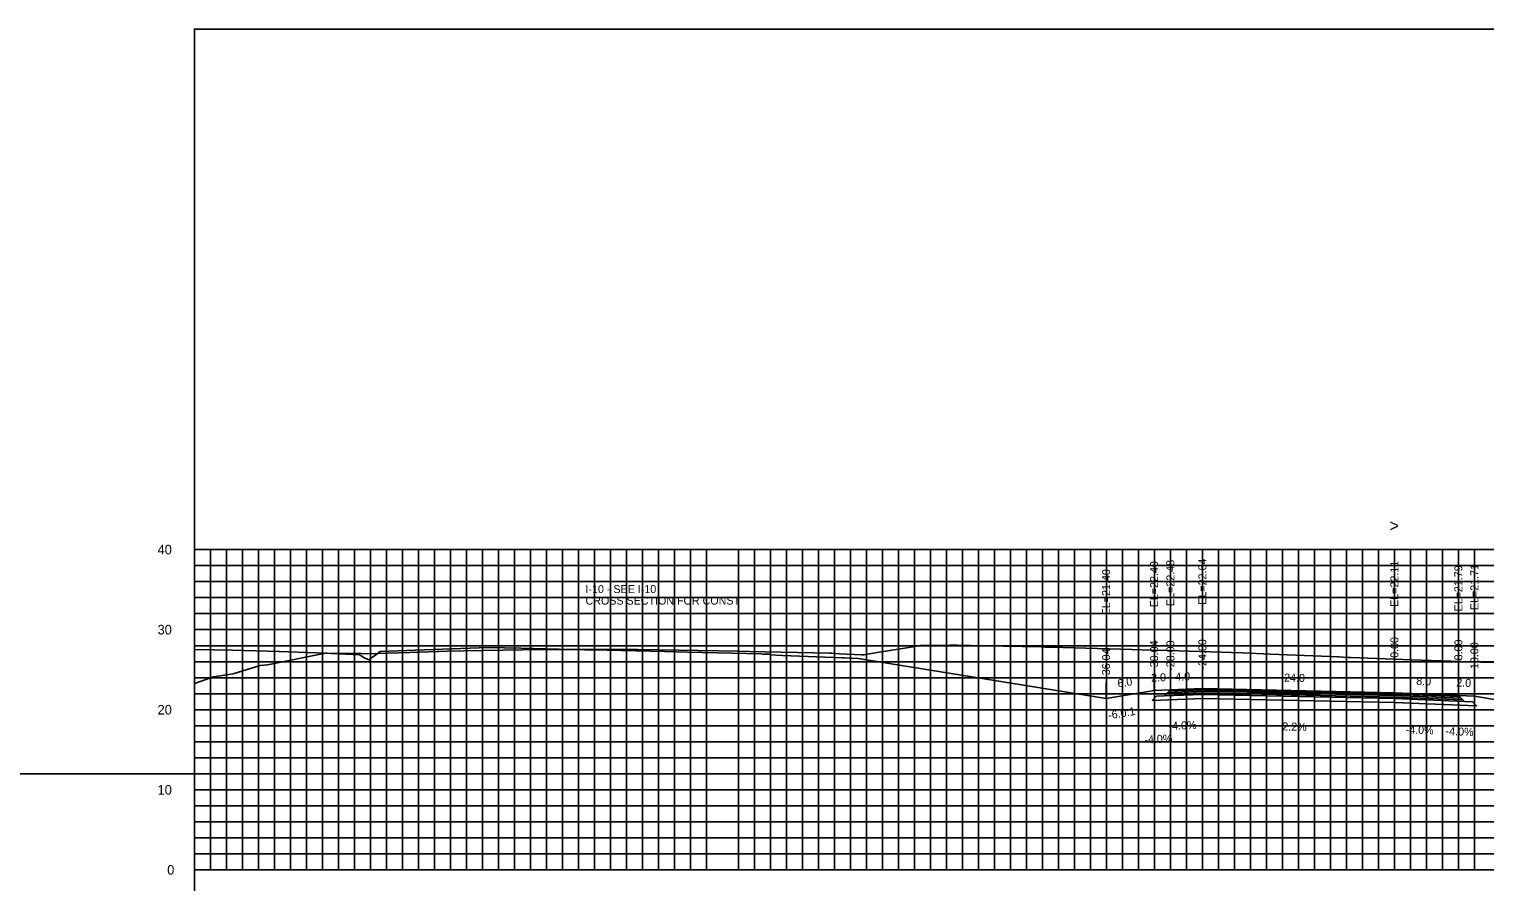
# Model space of a CAD drawing. Extents: x 1800976 to 1805104, y 250057 to 250580.
# Drawn here: x 1802800.3 to 1802982.3, y 250162.9 to 250269.4 of the extents above; entities that cross this region are included whole.
import ezdxf

# ---------------------------------------------------------------- set-up
doc = ezdxf.new("R2010")
doc.units = 0
for name, color, linetype in [('3', 7, 'Continuous'), ('31', 7, 'Continuous'), ('4', 7, 'Continuous'), ('60', 7, 'Continuous'), ('BASE', 7, 'Continuous'), ('CL-CNST', 7, 'Continuous'), ('Level 62', 7, 'Continuous'), ('LOWER BINDER', 7, 'Continuous'), ('M-ROADS', 7, 'Continuous'), ('UPPER BINDER', 7, 'Continuous'), ('WEARING', 7, 'Continuous')]:
    doc.layers.add(name, color=color, linetype=linetype)

msp = doc.modelspace()

# ---------------------------------------------------------------- linework, layer by layer
for p, q in [((1802940.96, 250186.83), (1802940.96, 250188.83)), ((1802943, 250186.91), (1802943, 250188.91)), ((1802947, 250187.07), (1802947, 250189.07)), ((1802971, 250186.54), (1802971, 250188.54)), ((1802934.96, 250185.83), (1802934.96, 250187.83)), ((1802979, 250186.22), (1802979, 250188.22)), ((1802981, 250186.14), (1802981, 250188.14))]:
    msp.add_line(p, q)
msp.add_lwpolyline([(1802821, 250079.43), (1803121, 250079.43), (1803121, 250269.43), (1802821, 250269.43)], close=True)
at = {"layer": '60'}
for p, q in [((1802820.94, 250204.43), (1802821, 250204.43)), ((1802821, 250164.43), (1802821, 250204.43)), ((1802820.94, 250194.43), (1802821, 250194.43)), ((1802820.94, 250184.43), (1802821, 250184.43)), ((1802820.94, 250174.43), (1802821, 250174.43)), ((1802820.94, 250164.43), (1802821, 250164.43)), ((1802821, 250164.43), (1803121, 250164.43)), ((1802821, 250164.37), (1802821, 250164.43)), ((1802831, 250164.37), (1802831, 250164.43)), ((1802841, 250164.37), (1802841, 250164.43)), ((1802851, 250164.37), (1802851, 250164.43)), ((1802861, 250164.37), (1802861, 250164.43)), ((1802871, 250164.37), (1802871, 250164.43)), ((1802881, 250164.37), (1802881, 250164.43)), ((1802891, 250164.37), (1802891, 250164.43)), ((1802901, 250164.37), (1802901, 250164.43)), ((1802911, 250164.37), (1802911, 250164.43)), ((1802921, 250164.37), (1802921, 250164.43)), ((1802931, 250164.37), (1802931, 250164.43)), ((1802941, 250164.37), (1802941, 250164.43)), ((1802951, 250164.37), (1802951, 250164.43)), ((1802961, 250164.37), (1802961, 250164.43)), ((1802971, 250164.37), (1802971, 250164.43)), ((1802981, 250164.37), (1802981, 250164.43))]:
    msp.add_line(p, q, dxfattribs=at)
at = {"layer": 'BASE'}
msp.add_lwpolyline([(1802941.25, 250186.12), (1802942.25, 250186.16), (1802947, 250186.35), (1802971, 250185.82), (1802979.75, 250185.47), (1802980.75, 250185.43), (1802981.27, 250184.91), (1802971, 250185.32), (1802947, 250185.85), (1802940.73, 250185.6)], close=True, dxfattribs=at)
at = {"layer": 'CL-CNST'}
for points in [[(1802821, 250191.96), (1802825.78, 250191.85), (1802831.59, 250191.72), (1802836.32, 250191.52), (1802841.69, 250191.3), (1802842.24, 250190.9), (1802842.95, 250190.61), (1802842.95, 250190.29), (1802842.95, 250190.77), (1802843.5, 250191.17), (1802844.21, 250191.69), (1802849.75, 250191.9), (1802857.71, 250192.2), (1802861.82, 250192.11), (1802869.79, 250191.92), (1802872.58, 250191.86), (1802879.77, 250191.69), (1802882.62, 250191.62), (1802891.88, 250191.4), (1802892.07, 250191.39), (1802892.88, 250191.36), (1802892.9, 250191.35), (1802892.96, 250191.29), (1802894.53, 250191.22), (1802901.96, 250190.92), (1802902.23, 250190.9), (1802903.98, 250190.83), (1802934.96, 250185.83)], [(1802934.96, 250185.83), (1802940.96, 250186.83), (1802943, 250186.91), (1802947, 250187.07), (1802971, 250186.54), (1802979, 250186.22), (1802981, 250186.14), (1803011, 250181.14), (1803015, 250181.14), (1803032.52, 250185.52)]]:
    msp.add_lwpolyline(points, dxfattribs=at)
at = {"layer": 'Level 62'}
for p, q in [((1802821, 250204.43), (1803121, 250204.43)), ((1802821, 250164.43), (1802821, 250204.43)), ((1802823, 250164.43), (1802823, 250204.43)), ((1802825, 250164.43), (1802825, 250204.43)), ((1802827, 250164.43), (1802827, 250204.43)), ((1802829, 250164.43), (1802829, 250204.43)), ((1802831, 250164.43), (1802831, 250204.43)), ((1802833, 250164.43), (1802833, 250204.43)), ((1802835, 250164.43), (1802835, 250204.43)), ((1802837, 250164.43), (1802837, 250204.43)), ((1802839, 250164.43), (1802839, 250204.43)), ((1802841, 250164.43), (1802841, 250204.43)), ((1802843, 250164.43), (1802843, 250204.43)), ((1802845, 250164.43), (1802845, 250204.43)), ((1802847, 250164.43), (1802847, 250204.43)), ((1802849, 250164.43), (1802849, 250204.43)), ((1802851, 250164.43), (1802851, 250204.43)), ((1802853, 250164.43), (1802853, 250204.43)), ((1802855, 250164.43), (1802855, 250204.43)), ((1802857, 250164.43), (1802857, 250204.43)), ((1802859, 250164.43), (1802859, 250204.43)), ((1802861, 250164.43), (1802861, 250204.43)), ((1802863, 250164.43), (1802863, 250204.43)), ((1802865, 250164.43), (1802865, 250204.43)), ((1802867, 250164.43), (1802867, 250204.43)), ((1802869, 250164.43), (1802869, 250204.43)), ((1802871, 250164.43), (1802871, 250204.43)), ((1802873, 250164.43), (1802873, 250204.43)), ((1802875, 250164.43), (1802875, 250204.43)), ((1802877, 250164.43), (1802877, 250204.43)), ((1802879, 250164.43), (1802879, 250204.43)), ((1802881, 250164.43), (1802881, 250204.43)), ((1802883, 250164.43), (1802883, 250204.43)), ((1802885, 250164.43), (1802885, 250204.43)), ((1802889, 250164.43), (1802889, 250204.43)), ((1802891, 250164.43), (1802891, 250204.43)), ((1802893, 250164.43), (1802893, 250204.43)), ((1802895, 250164.43), (1802895, 250204.43)), ((1802897, 250164.43), (1802897, 250204.43)), ((1802899, 250164.43), (1802899, 250204.43)), ((1802901, 250164.43), (1802901, 250204.43)), ((1802903, 250164.43), (1802903, 250204.43)), ((1802905, 250164.43), (1802905, 250204.43)), ((1802907, 250164.43), (1802907, 250204.43)), ((1802909, 250164.43), (1802909, 250204.43)), ((1802911, 250164.43), (1802911, 250204.43)), ((1802913, 250164.43), (1802913, 250204.43)), ((1802915, 250164.43), (1802915, 250204.43)), ((1802917, 250164.43), (1802917, 250204.43)), ((1802919, 250164.43), (1802919, 250204.43)), ((1802921, 250164.43), (1802921, 250204.43)), ((1802923, 250164.43), (1802923, 250204.43)), ((1802925, 250164.43), (1802925, 250204.43)), ((1802927, 250164.43), (1802927, 250204.43)), ((1802929, 250164.43), (1802929, 250204.43)), ((1802931, 250164.43), (1802931, 250204.43)), ((1802933, 250164.43), (1802933, 250204.43)), ((1802935, 250164.43), (1802935, 250204.43)), ((1802937, 250164.43), (1802937, 250204.43)), ((1802939, 250164.43), (1802939, 250204.43)), ((1802941, 250164.43), (1802941, 250204.43)), ((1802943, 250164.43), (1802943, 250204.43)), ((1802945, 250164.43), (1802945, 250204.43)), ((1802947, 250164.43), (1802947, 250204.43)), ((1802949, 250164.43), (1802949, 250204.43)), ((1802951, 250164.43), (1802951, 250204.43)), ((1802953, 250164.43), (1802953, 250204.43)), ((1802955, 250164.43), (1802955, 250204.43)), ((1802957, 250164.43), (1802957, 250204.43)), ((1802959, 250164.43), (1802959, 250204.43)), ((1802961, 250164.43), (1802961, 250204.43)), ((1802963, 250164.43), (1802963, 250204.43)), ((1802965, 250164.43), (1802965, 250204.43)), ((1802967, 250164.43), (1802967, 250204.43)), ((1802969, 250164.43), (1802969, 250204.43)), ((1802971, 250164.43), (1802971, 250204.43)), ((1802973, 250164.43), (1802973, 250204.43)), ((1802975, 250164.43), (1802975, 250204.43)), ((1802977, 250164.43), (1802977, 250204.43)), ((1802979, 250164.43), (1802979, 250204.43)), ((1802981, 250164.43), (1802981, 250204.43)), ((1802821, 250202.43), (1803121, 250202.43)), ((1802821, 250200.43), (1803121, 250200.43)), ((1802821, 250198.43), (1803121, 250198.43)), ((1802821, 250196.43), (1803121, 250196.43)), ((1802821, 250194.43), (1803121, 250194.43)), ((1802821, 250192.43), (1803121, 250192.43)), ((1802821, 250190.43), (1803121, 250190.43)), ((1802821, 250188.43), (1803121, 250188.43)), ((1802821, 250186.43), (1803121, 250186.43)), ((1802821, 250184.43), (1803121, 250184.43)), ((1802821, 250182.43), (1803121, 250182.43)), ((1802821, 250180.43), (1803121, 250180.43)), ((1802821, 250178.43), (1803121, 250178.43)), ((1802481, 250176.43), (1802929.9, 250176.43)), ((1802821, 250176.43), (1803121, 250176.43)), ((1802821, 250174.43), (1803121, 250174.43)), ((1802821, 250172.43), (1803121, 250172.43)), ((1802821, 250170.43), (1803121, 250170.43)), ((1802821, 250168.43), (1803121, 250168.43)), ((1802821, 250166.43), (1803121, 250166.43)), ((1802821, 250164.43), (1803121, 250164.43))]:
    msp.add_line(p, q, dxfattribs=at)
at = {"layer": 'LOWER BINDER'}
for points in [[(1802947, 250186.54), (1802971, 250186.01), (1802979.55, 250185.67), (1802979.75, 250185.47), (1802971, 250185.82), (1802947, 250186.35), (1802942.25, 250186.16), (1802942.45, 250186.36)], [(1802947, 250186.73), (1802971, 250186.2), (1802979.36, 250185.87), (1802979.55, 250185.67), (1802971, 250186.01), (1802947, 250186.54), (1802942.45, 250186.36), (1802942.65, 250186.56)]]:
    msp.add_lwpolyline(points, close=True, dxfattribs=at)
at = {"layer": 'M-ROADS'}
msp.add_lwpolyline([(1802821, 250187.71), (1802823.38, 250188.53), (1802825.86, 250188.91), (1802829.21, 250189.97), (1802830.13, 250190.03), (1802837.41, 250191.5), (1802837.45, 250191.5), (1802837.46, 250191.5), (1802837.54, 250191.5), (1802841.84, 250191.46), (1802842.63, 250191.42), (1802849.14, 250191.63), (1802851.35, 250191.71), (1802851.54, 250191.71), (1802852.6, 250191.73), (1802854.63, 250191.77), (1802864.49, 250191.96), (1802870.56, 250191.95), (1802876.44, 250191.94), (1802881.46, 250191.86), (1802889.02, 250191.75), (1802890.36, 250191.72), (1802900.41, 250191.51), (1802900.7, 250191.49), (1802901.66, 250191.43), (1802904.45, 250191.29), (1802904.68, 250191.27), (1802906.36, 250191.56), (1802910.56, 250192.26), (1802911.77, 250192.47), (1802915.48, 250192.48), (1802916.41, 250192.48), (1802919.78, 250192.42), (1802926.85, 250192.28), (1802927.34, 250192.26), (1802928.09, 250192.23), (1802938.23, 250191.95), (1802940.67, 250191.88), (1802942.72, 250191.82), (1802951.97, 250191.54), (1802955.53, 250191.39), (1802964.02, 250191.02), (1802964.04, 250191.02), (1802964.55, 250191), (1802965.24, 250190.97), (1802965.27, 250190.97), (1802965.55, 250190.96), (1802973.14, 250190.66), (1802981.8, 250190.36), (1802982.04, 250190.36), (1802982.1, 250190.36), (1802982.19, 250190.35), (1802982.3, 250190.35), (1802984.78, 250190.35)], dxfattribs=at)
at = {"layer": 'UPPER BINDER'}
msp.add_lwpolyline([(1802979.36, 250185.87), (1802979.16, 250186.07), (1802971, 250186.39), (1802947, 250186.92), (1802942.85, 250186.75), (1802942.65, 250186.56), (1802947, 250186.73), (1802971, 250186.2)], close=True, dxfattribs=at)
at = {"layer": 'WEARING'}
msp.add_lwpolyline([(1802979.16, 250186.07), (1802979, 250186.22), (1802971, 250186.54), (1802947, 250187.07), (1802943, 250186.91), (1802942.85, 250186.75), (1802947, 250186.92), (1802971, 250186.39)], close=True, dxfattribs=at)

# ---------------------------------------------------------------- texts
msp.add_text('-6.0:1', height=1, rotation=9.4623).set_placement((1802935.31, 250183.23))
at = {"layer": '3'}
for s, p in [('EL=22.40', (1802941.46, 250197.22)), ('EL=22.48', (1802943.5, 250197.38)), ('EL=22.64', (1802947.5, 250197.54)), ('EL=22.11', (1802971.5, 250197.27)), ('EL=21.40', (1802935.46, 250196.22)), ('EL=21.79', (1802979.5, 250196.7)), ('EL=21.71', (1802981.5, 250196.87)), ('-36.04', (1802935.46, 250188.29)), ('-30.04', (1802941.46, 250189.29)), ('-28.00', (1802943.5, 250189.29)), ('-24.00', (1802947.5, 250189.45)), ('0.00', (1802971.5, 250190.91)), ('8.00', (1802979.5, 250190.59)), ('10.00', (1802981.5, 250189.51))]:
    msp.add_text(s, height=1, rotation=90, dxfattribs=at).set_placement(p)
for s, p in [('I-10 - SEE I-10 ', (1802869.89, 250199)), ('CROSS SECTION FOR CONST ', (1802869.89, 250197.56))]:
    msp.add_text(s, height=1, dxfattribs=at).set_placement(p)
at = {"layer": '31'}
for s, p in [('40', (1802816.4, 250203.83)), ('30', (1802816.4, 250193.83)), ('20', (1802816.4, 250183.83)), ('10', (1802816.4, 250173.83)), ('0', (1802817.6, 250163.83))]:
    msp.add_text(s, height=1.2, dxfattribs=at).set_placement(p)
at = {"layer": '4'}
for s, rotation, p in [('6.0', 9.4623, (1802936.47, 250187.2)), ('2.0', 2.2906, (1802940.61, 250187.92)), ('4.0', 2.2906, (1802943.64, 250188.04)), ('24.0', 358.7397, (1802957.21, 250187.95)), ('8.0', 357.7094, (1802973.72, 250187.54)), ('2.0', 357.7094, (1802978.72, 250187.34)), ('-4.0%', 2.2906, (1802942.79, 250181.9)), ('2.2%', 358.7397, (1802956.98, 250181.85)), ('-4.0%', 2.2906, (1802939.77, 250180.21)), ('-4.0%', 357.7094, (1802972.39, 250181.48)), ('-4.0%', 357.7094, (1802977.39, 250181.28))]:
    msp.add_text(s, height=1, rotation=rotation, dxfattribs=at).set_placement(p)
at = {"layer": '60'}
for s, height, p in [('>', 1.5, (1802970.39, 250206.68)), ('-', 0.0001, (1802821, 250164.43))]:
    msp.add_text(s, height=height, dxfattribs=at).set_placement(p)

doc.saveas('drawing.dxf')
